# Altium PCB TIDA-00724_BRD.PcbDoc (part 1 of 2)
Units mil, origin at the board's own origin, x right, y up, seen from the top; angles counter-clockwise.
Board outline 4500 x 3350 mil, 4 copper layers (Top Layer, Signal Layer 1, Signal Layer 2, Bottom Layer), stack 61.634 mil thick; 147 components, 76 nets, 383 pads, 213 vias.
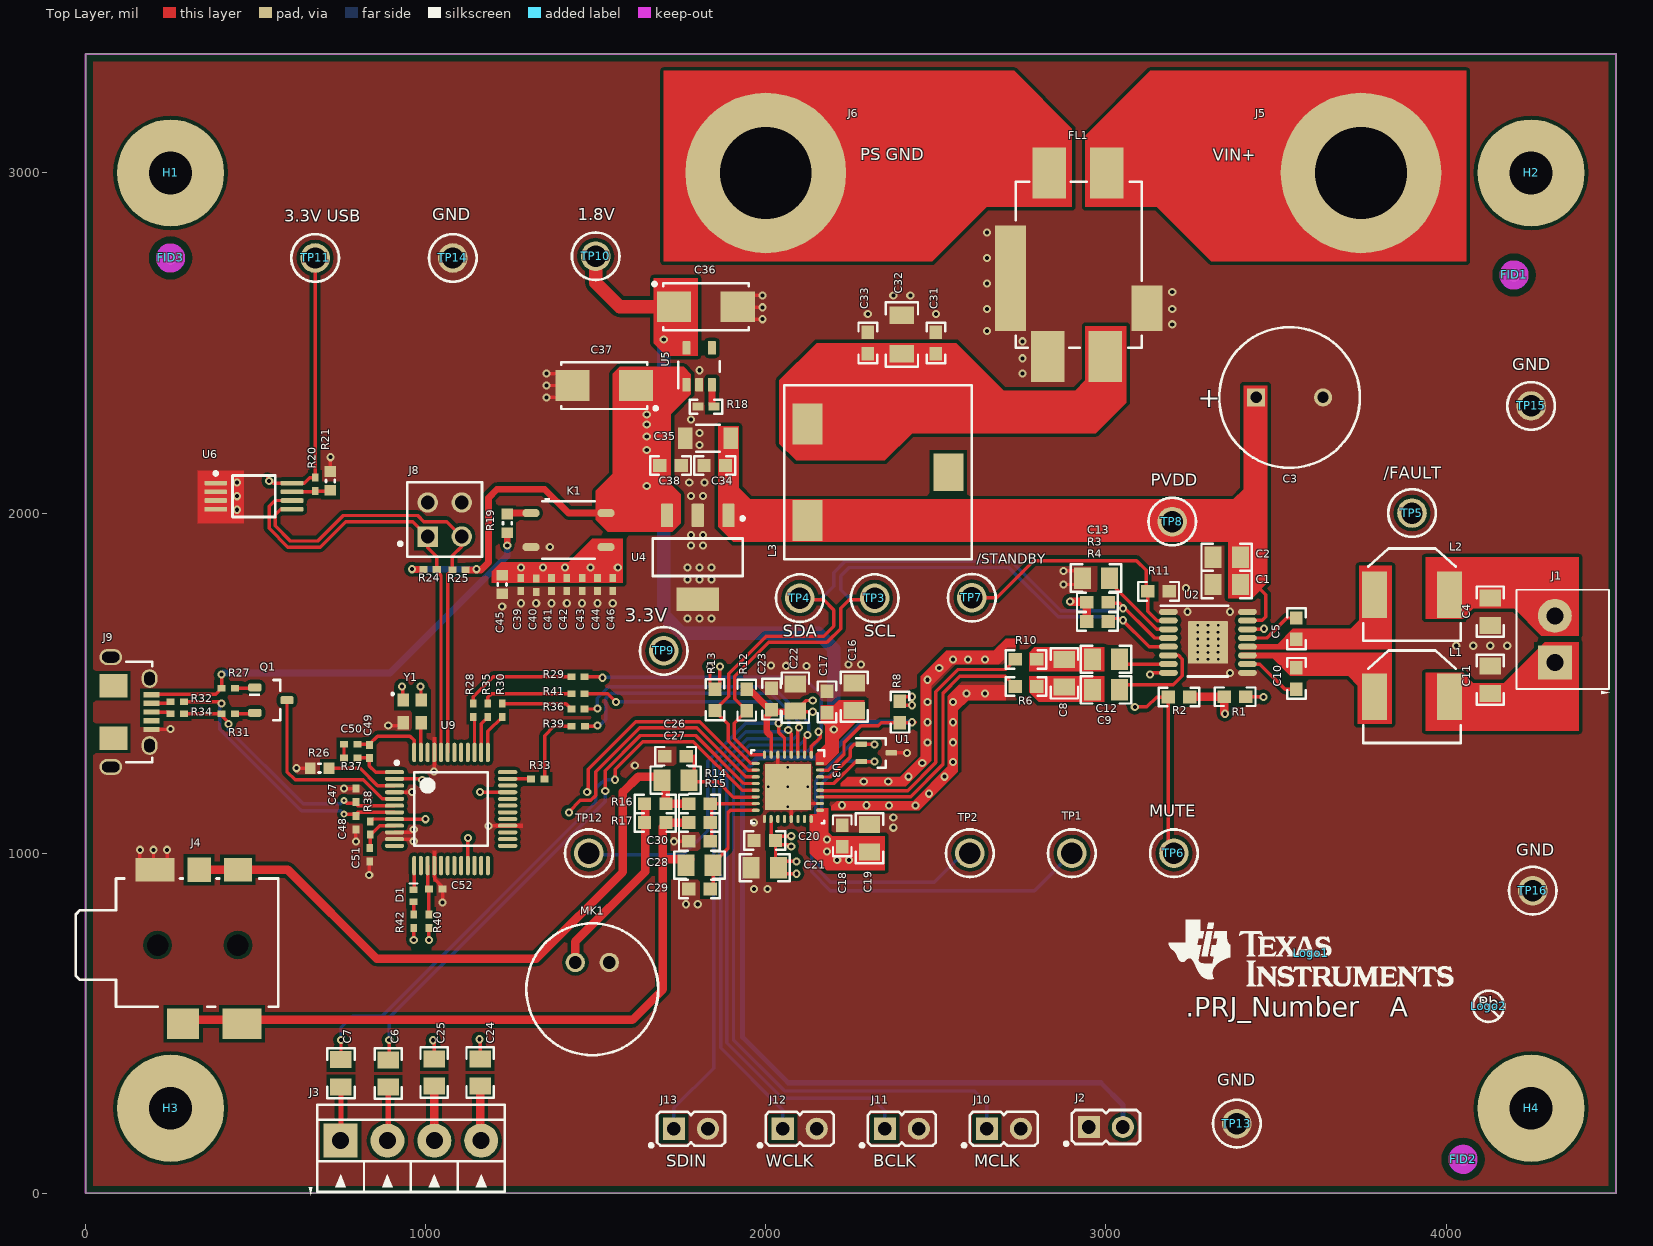
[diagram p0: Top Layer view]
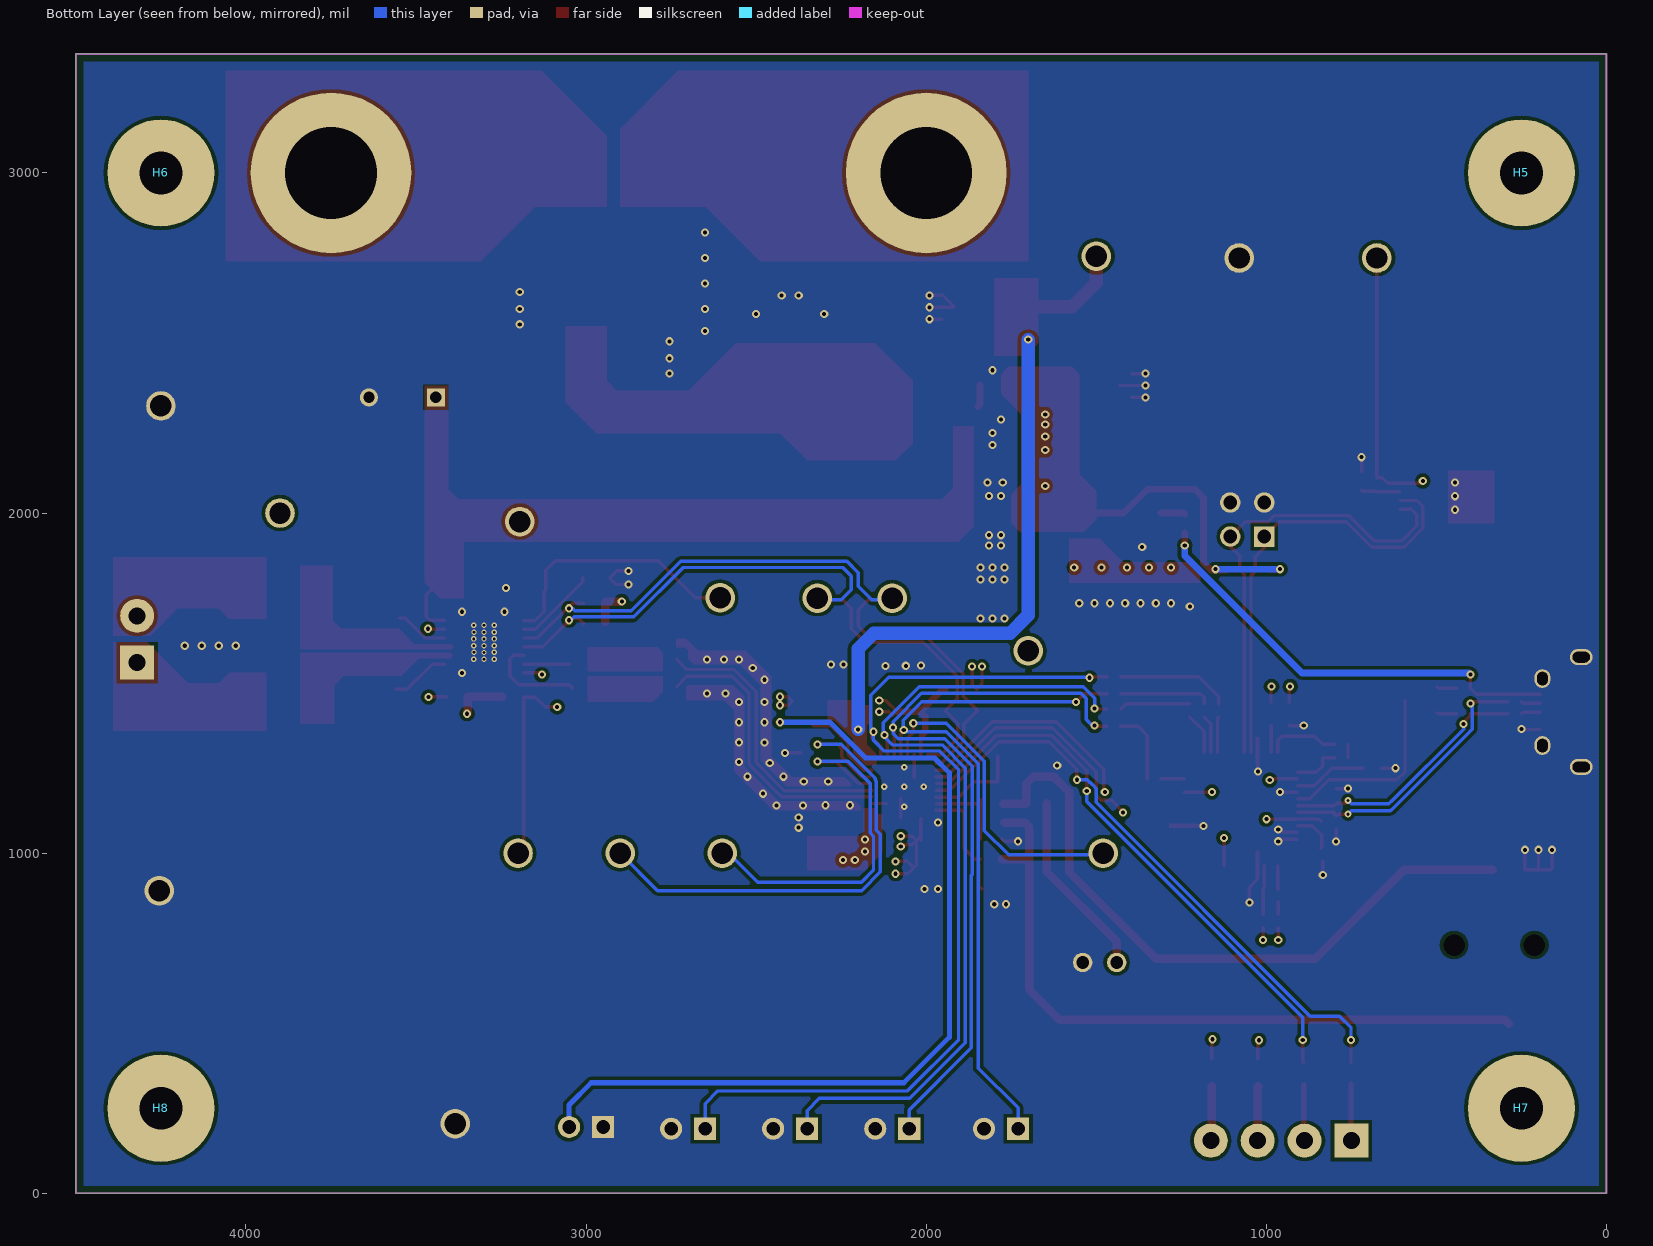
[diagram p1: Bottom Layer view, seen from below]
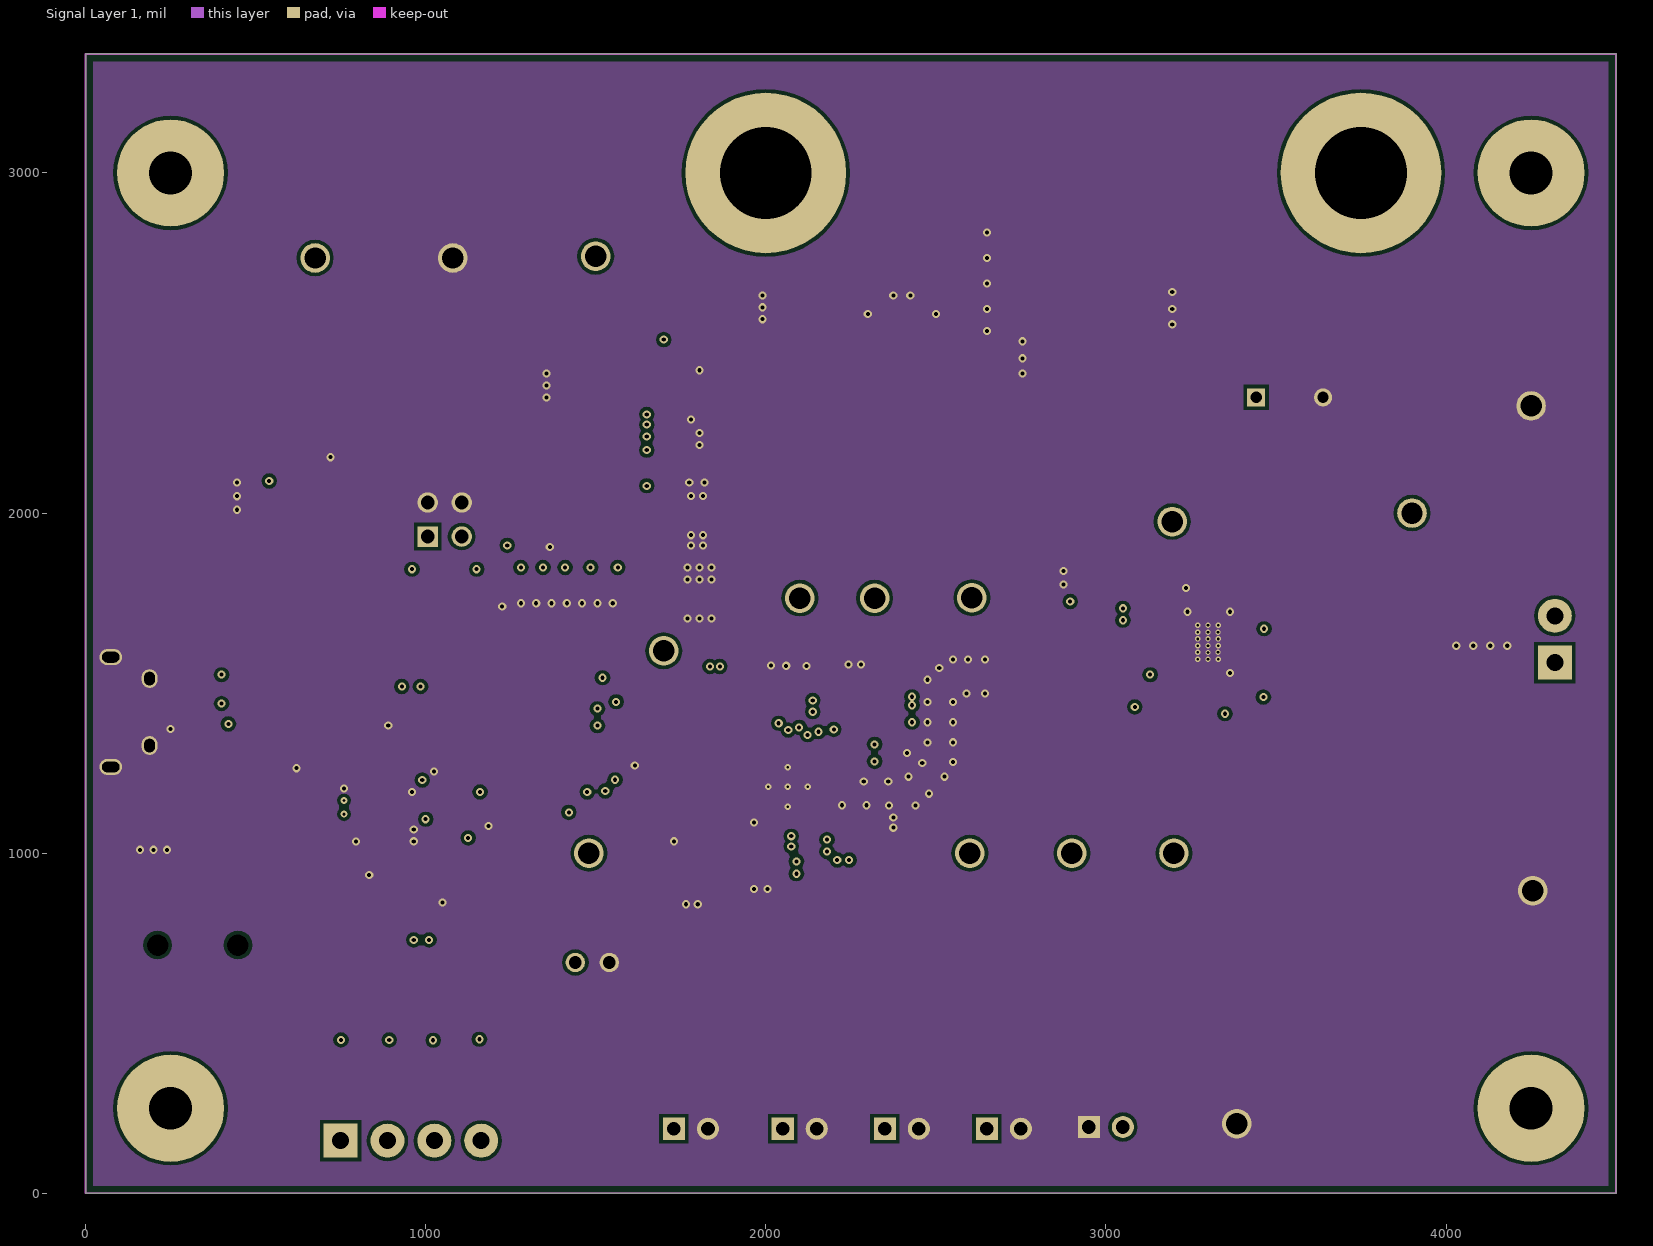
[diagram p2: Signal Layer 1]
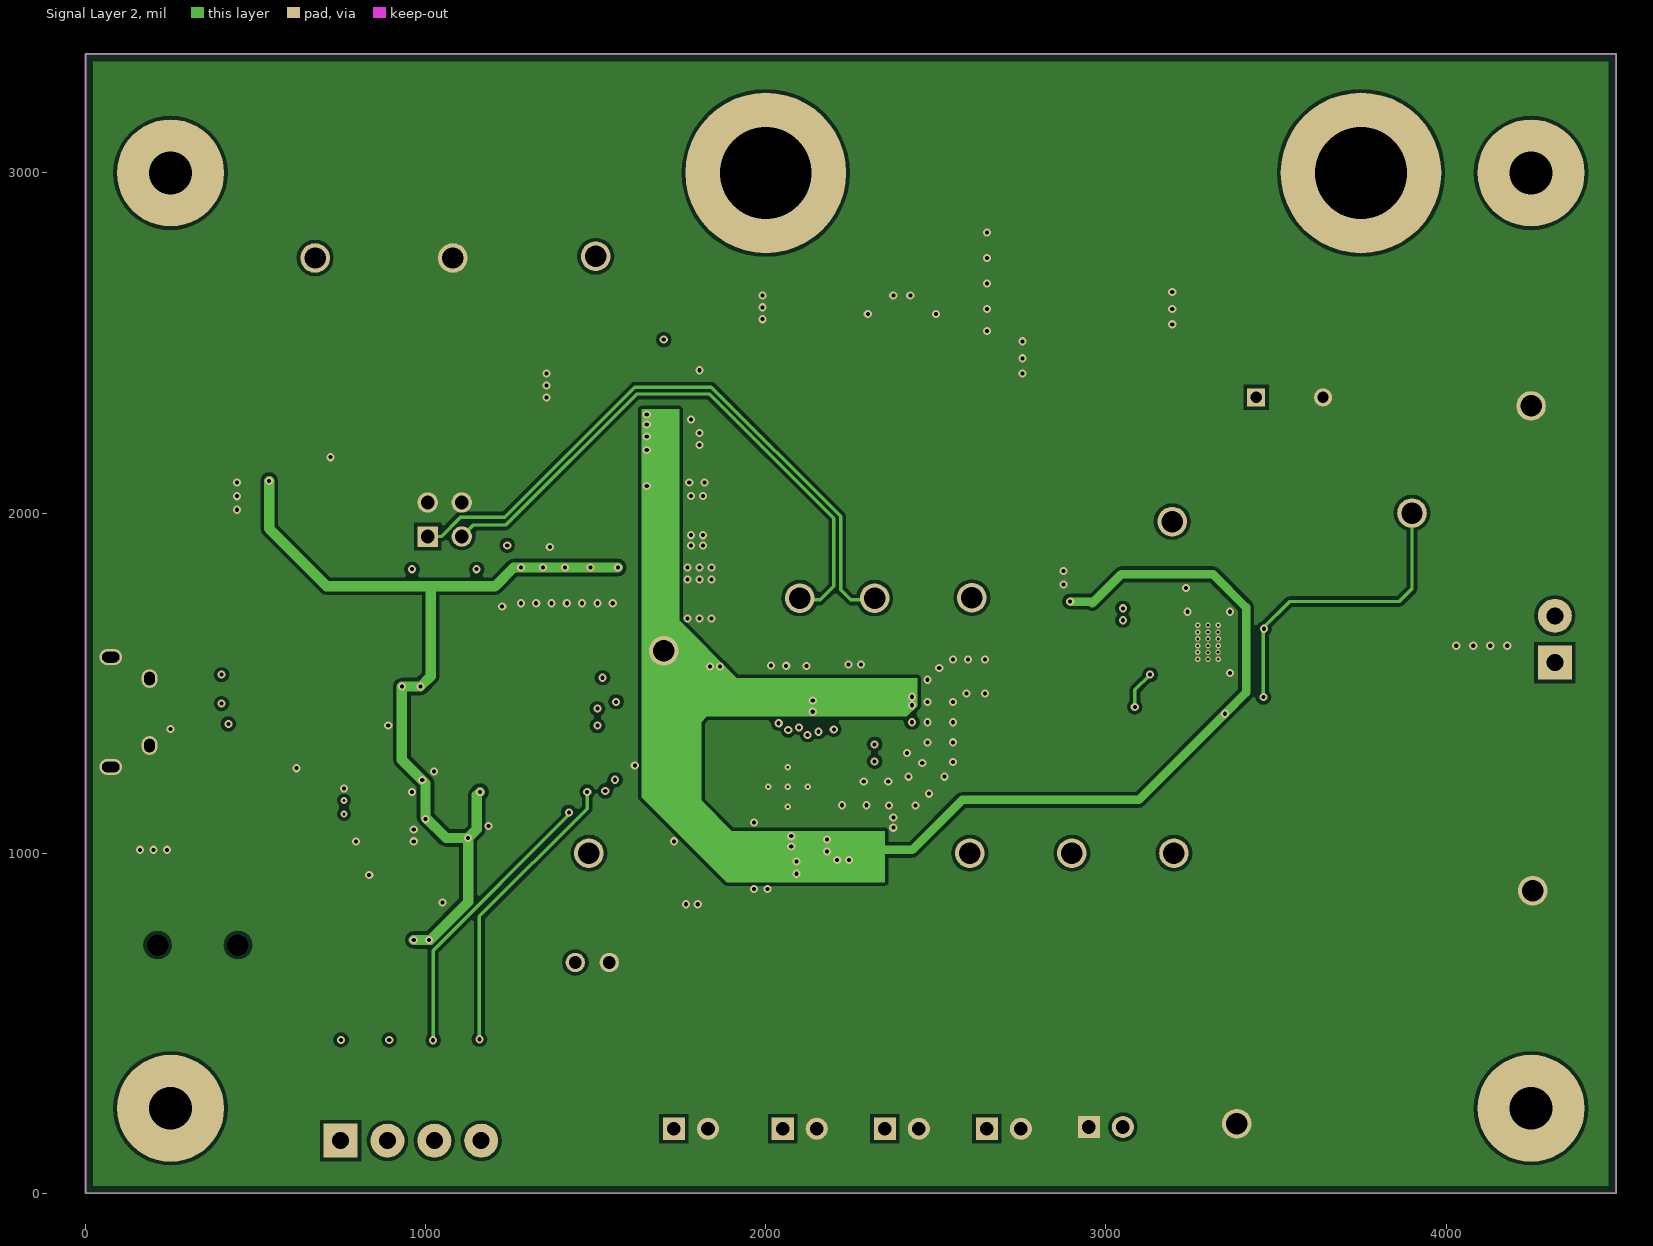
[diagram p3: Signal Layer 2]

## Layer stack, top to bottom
Top Solder: solder mask 0.4, Solder Resist, Dk 3.5
Top Layer: signal copper 1.4
Dielectric1: prepreg 13, FR-4, Dk 4.2
Signal Layer 1: signal copper 1.417
Dielectric 3: core 30, FR-4, Dk 4.2
Signal Layer 2: signal copper 1.417
Dielectric 2: prepreg 13, FR-4, Dk 4.2
Bottom Layer: signal copper 1.4
Bottom Solder: solder mask 0.4, Solder Resist, Dk 3.5

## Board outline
0,0 0,3350 4500,3350 4500,0

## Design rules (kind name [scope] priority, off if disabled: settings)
AcuteAngle [All] p1: minimum=4.50000000000000E+0001 checktracksonly=FALSE
AssemblyTestPointUsage [All] p1: valid=2
Clearance Clearance_Keepouts [((IsTrack Or IsArc) And Not InPoly) And IsFree and IsKeepOut vs ((IsTrack Or IsArc) And Not InPoly) And IsFree and IsKeepOut] p1: gap=0
Clearance Clearance_BoardEdge_MountingHoles [OnCopper and InComponentClass('Mounting Holes') vs IsKeepOut] p2: gap=20
Clearance Clearance_BoardEdge_Poly [OnCopper and InPoly vs IsKeepOut] p3: gap=20
Clearance Clearance_BoardEdge [OnCopper and Not InComponentClass('Logo') and not InComponentClass('FiducialMark') and not InRegion(1000,500,4000,800) and Not IsKeepout vs IsKeepOut] p4: gap=20
Clearance Clearance_Poly [InPolygon] p5: gap=10
Clearance [All] p6: gap=7.87
ComponentClearance ComponentClearance_MountingHoles_FiducialMarks [InComponentClass('Mounting Holes') vs InComponentClass('FiducialMark')] p1: gap=20 collisioncheckmode=3 verticalgap=10 showdistances=FALSE
ComponentClearance ComponentClearance_Shunt [InComponentClass('Header') vs InComponentClass('Shunt')] p2: gap=0 collisioncheckmode=3 verticalgap=0 showdistances=FALSE
ComponentClearance ComponentClearance_Logo [InComponentClass('Logo')] p3: gap=20 collisioncheckmode=3 verticalgap=10 showdistances=FALSE
ComponentClearance ComponentClearance_ScrewToNut [(HasFootprint('NY PMS 440 0025 PH')) vs (HasFootprint('Keystone_1902C'))] p4: gap=5 collisioncheckmode=3 verticalgap=10 showdistances=FALSE
ComponentClearance ComponentClearance_MountingHoles [InComponentClass('Mounting Holes')] p5: gap=20 collisioncheckmode=3 verticalgap=20 showdistances=FALSE
ComponentClearance ComponentClearance_SmallPassives [HasFootprint('0201*') or HasFootprint('0402*') or HasFootprint('0508') or HasFootprint('0603*') or HasFootprint('0612') or HasFootprint('0805*') or HasFootprint('0815*') or HasFootprint('0830*') or HasFootprint('1206*') or HasFootprint('1210*') or HasFootprint('1808*') or HasFootprint('1812*') or HasFootprint('1825*') or HasFootprint('2010*') or HasFootprint('2220*') or HasFootprint('2225*') or HasFootprint('2512*') or HasFootprint('2728*') or HasFootprint('3518*') vs HasFootprint('0201*') or HasFootprint('0402*') or HasFootprint('0508') or HasFootprint('0603*') or HasFootprint('0612') or HasFootprint('0805*') or HasFootprint('0815*') or HasFootprint('0830*') or HasFootprint('1206*') or HasFootprint('1210*') or HasFootprint('1808*') or HasFootprint('1812*') or HasFootprint('1825*') or HasFootprint('2010*') or HasFootprint('2220*') or HasFootprint('2225*') or HasFootprint('2512*') or HasFootprint('2728*') or HasFootprint('3518*')] p6: gap=10 collisioncheckmode=3 verticalgap=10 showdistances=FALSE
ComponentClearance ComponentClearance_THtoSMT [IsThruComponent vs IsSMTComponent] p7: gap=20 collisioncheckmode=3 verticalgap=30 showdistances=FALSE
ComponentClearance ComponentClearance_THtoTH [IsThruComponent vs IsThruComponent] p8: gap=20 collisioncheckmode=3 verticalgap=30 showdistances=FALSE
ComponentClearance [All] p9: gap=20 collisioncheckmode=3 verticalgap=10 showdistances=FALSE
DiffPairsRouting [All] p1: maxlimit=100 minlimit=10 mostfreqgap=10 toplayer_minwidth=15 toplayer_maxwidth=15 toplayer_prefwidth=15 midlayer1_minwidth=15 midlayer1_maxwidth=15 midlayer1_prefwidth=15 midlayer2_minwidth=15 midlayer2_maxwidth=15 midlayer2_prefwidth=15 bottomlayer_minwidth=15 bottomlayer_maxwidth=15 bottomlayer_prefwidth=15 maxuncoupledlength=1000
FabricationTestPointUsage TestPointUsage [All] p1: valid=2 allowmultiple=FALSE
FabricationTestpoint Testpoint [All] p1: side=3 testpointundercomponent=TRUE minsize=40 maxsize=100 preferedsize=60 minholesize=0 maxholesize=40 preferedholesize=32 testpointgrid=1 allowsidetop=TRUE allowsidebottom=TRUE usegrid=TRUE gridtolerance=0.01
FanoutControl Fanout_LCC [IsLCC] p1: bgadir=Out bgaviamode=Centered fanoutstyle=Auto fanoutdirection=Alternating viagrid=1 // Fanout_LCC (Default Rule)
FanoutControl Fanout_BGA [IsBGA] p2: bgadir=Out bgaviamode=Centered fanoutstyle=Auto fanoutdirection=Alternating viagrid=1 // Fanout_BGA (Default Rule)
FanoutControl Fanout_Default [All] p4: bgadir=Out bgaviamode=Centered fanoutstyle=Auto fanoutdirection=Alternating viagrid=1 // Fanout_Default (Default Rule)
FanoutControl Fanout_Small [(CompPinCount < 5)] p5: bgadir=Out bgaviamode=Centered fanoutstyle=Auto fanoutdirection=OutThenIn viagrid=1 // Fanout_Small (Default Rule)
HoleSize [All] p1: absolutevalues=TRUE maxlimit=300 minlimit=5 maxpercent=80.000 minpercent=20.000
MinimumAnnularRing MinimumAnnularRing_ThermalPadVias [IsVia and InAnyComponent] p1: minimumring=3
MinimumAnnularRing [All] p2: minimumring=3
MinimumSolderMaskSliver MinimumSolderMaskSliver_Logo [InComponentClass('Logo') vs InComponentClass('Logo')] p1: minsoldermaskwidth=0.7
MinimumSolderMaskSliver [All] p2: minsoldermaskwidth=3
PlaneClearance [All] p1: clearance=10
PlaneConnect [All] p1: planeconnectstyle=Direct reliefexpansion=10 reliefentries=4 reliefconductorwidth=10 reliefairgap=10
PolygonConnect [All] p1: connectstyle=Direct reliefconductorwidth=10 reliefentries=4 polygonreliefangle="90 Angle" airgapwidth=10
RoutingVias ThermalPadVias [IsVia and InAnyComponent] p1: holewidth=7.87 width=19.68 viastyle="Through Hole" minholewidth=5 minwidth=15 maxholewidth=12.99 maxwidth=23.62
RoutingVias [All] p2: holewidth=16 width=34 viastyle="Through Hole" minholewidth=5 minwidth=15 maxholewidth=40 maxwidth=65
SilkToBoardRegionClearance [Not ((IsComment or IsDesignator) And (Hide <> 'False')) and not InRegion(1000,500,4000,800)] p1:
SilkToSilkClearance SilkToSilkClearance_Pb-FreeLogo [(HasFootprint('Pb-Free_Overlay_Medium') OR HasFootprint('Pb-Free_Overlay_Small')) vs (HasFootprint('Pb-Free_Overlay_Medium') OR HasFootprint('Pb-Free_Overlay_Small'))] p1: silktosilkclearance=0
SilkToSilkClearance [All] p2: silktosilkclearance=4
SilkToSolderMaskClearance "Silk to Solder Mask Opening" [All] p1: minsilkscreentomaskgap=2.5 clearancetoexposedcopper=FALSE
SolderMaskExpansion [All] p1: expansion=1.97
UnpouredPolygon [All] p1: allowunpoured=FALSE
Width [All] p1: maxlimit=100 minlimit=6 preferedwidth=10 checkconnectedcopper=TRUE
13 further rules are at their usual default settings.

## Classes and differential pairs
component class AssemblyNote: ZZ1 ZZ2 ZZ3
component class FiducialMark: FID1 FID2 FID3
component class eCall_Audio_Hardware: FID1 FID2 FID3 H1 H2 H3 H4 H5 H6 H7 H8 Logo1 Logo2 ZZ1 ZZ2 ZZ3
component class Logo: Logo1
component class "Mounting Holes": H1 H2 H3 H4
component class eCall_Audio: C1 C2 C3 C4 C5 C6 C7 C8 C9 C10 C11 C12 C13 C16 C17 C18 C19 C20 C21 C22 C23 C24 C25 C26 C27 C28 C29 C30 J1 J2 J3 J4 L1 L2 MK1 R1 R2 R3 R4 R6 R8 R10 R11 R12 R13 R14 R15 R16 R17 TP1 TP2 TP3 TP4 TP5 TP6 TP7 TP12 U1 U2 U3
component class Header: J2 J8 J10 J11 J12 J13
component class eCall_Audio_Power: C31 C32 C33 C34 C35 C36 C37 C38 FL1 J5 J6 L3 R18 TP8 TP9 TP10 U4 U5
component class eCall_Audio_TAS1020: C39 C40 C41 C42 C43 C44 C45 C46 C47 C48 C49 C50 C51 C52 D1 J8 J9 J10 J11 J12 J13 K1 Q1 R19 R20 R21 R24 R25 R26 R27 R28 R29 R30 R31 R32 R33 R34 R35 R36 R37 R38 R39 R40 R41 R42 TP11 TP13 TP14 TP15 TP16 U6 U9 Y1

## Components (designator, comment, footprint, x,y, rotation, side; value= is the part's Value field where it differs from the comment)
C1 "C0805C106K9PAC" 0805_HV 3355,1790 r180 top
C2 "GRM21BR71H105KA12L" 0805_HV 3355,1870 r180 top
C3 "EKZE500ELL331MJ25S" KZE_1000x2500 3540,2340 r0 top
C4 "EMK212B7225KG-T" 0805_HV 4130,1710 r90 top
C5 "C1608X7R1H224K080AB" 0603 3560,1660 r90 top
C6 "C2012X7R2A104K" 0805_HV 890,352 r90 top
C7 "C2012X7R2A104K" 0805_HV 751,353 r90 top
C8 "EMK212B7225KG-T" 0805_HV 2878,1529 r90 top
C9 "EMK212B7225KG-T" 0805_HV 3000,1480 r180 top
C10 "C1608X7R1H224K080AB" 0603 3560,1514 r270 top
C11 "EMK212B7225KG-T" 0805_HV 4130,1510 r90 top
C12 "EMK212B7225KG-T" 0805_HV 3000,1570 r180 top
C13 "GRM21BR71H105KA12L" 0805_HV 2971,1809 r180 top
C16 "C0805C106K9PAC" 0805_HV 2260,1460 r90 top
C17 "C1608X7R1C104K" 0603 2180,1445 r90 top
C18 "C1608X7R1C104K" 0603 2225,1051 r90 top
C19 "C0805C106K9PAC" 0805_HV 2305,1044 r90 top
C20 "C1608X7R1C104K" 0603 1997.01,1037.46 r180 top
C21 "C0805C106K9PAC" 0805_HV 1997.01,957.46 r180 top
C22 "C0805C106K9PAC" 0805_HV 2087.01,1457.46 r90 top
C23 "C1608X7R1C104K" 0603 2017,1453 r90 top
C24 "C2012X7R2A104K" 0805_HV 1160,355 r90 top
C25 "C2012X7R2A104K" 0805_HV 1025,355 r90 top
C26 "DNP" 0603 1735,1285 r180 top
C27 "C2012X7R2A104K" 0805_HV 1735,1215 r0 top
C28 "C2012X7R2A104K" 0805_HV 1805,965 r0 top
C29 "DNP" 0603 1805,895 r180 top
C30 "DNP" 0603 1805,1035 r180 top
C31 "GRM188R71H222KA01D" 0603 2500,2500 r90 top
C32 "GRM31CR71E475KA88L" 1206 2400,2525 r90 top
C33 "GRM188R71E823KA01D" 0603 2300,2500 r90 top
C34 "GRM188R71E104KA01D" 0603 1850,2140 r180 top
C35 "GRM31CR61H106KA12L" 1206_190 1830,2220 r180 top
C36 "TPSC475K035R0600" 6032-28 1824.05,2606.56 r0 top
C37 "TPSC475K035R0600" 6032-28 1525,2375 r180 top
C38 "GRM188R71E104KA01D" 0603 1720,2140 r0 top
C39 "GRM155R71C104KA88D" 0402L 1280,1790 r270 top
C40 "GRM155R71C104KA88D" 0402L 1325,1788.19 r270 top
C41 "GRM155R71C104KA88D" 0402L 1370,1790 r270 top
C42 "GRM155R71C104KA88D" 0402L 1415,1790 r270 top
C43 "GRM155R71C104KA88D" 0402L 1460,1790 r270 top
C44 "GRM155R71C104KA88D" 0402L 1505,1790 r270 top
C45 "C1608X5R1A106M" 0603L 1225,1790 r270 top
C46 "C1005X5R0J105M" 0402L 1550,1790 r90 top
C47 "GRM1555C1E470JA01D" 0402L 795,1170 r270 top
C48 "GRM1555C1E470JA01D" 0402L 795,1090 r90 top
C49 "GRM1555C1H101JA01D" 0402L 835,1299 r90 top
C50 "GRM1555C1H102JA01D" 0402L 779.69,1320 r180 top
C51 "C1005X5R0J105M" 0402L 836,995 r90 top
C52 "GRM155R71C104KA88D" 0402L 1029.69,895 r0 top
D1 "USB-LOCK" LED_SMLP12_BLUE 964.69,875 r90 top
FID1 "Fiducial" Fiducial10-20 4200,2700 r0 top
FID2 "Fiducial" Fiducial10-20 4050,100 r0 top
FID3 "Fiducial" Fiducial10-20 250,2750 r0 top
FL1 "BNX022-01L" FIL_BNX02X 2920,2730 r270 top
H1 "NY PMS 440 0025 PH" "NY PMS 440 0025 PH" 250,3000 r0 top locked
H2 "NY PMS 440 0025 PH" "NY PMS 440 0025 PH" 4250,3000 r0 top locked
H3 "NY PMS 440 0025 PH" "NY PMS 440 0025 PH" 250,250 r0 top locked
H4 "NY PMS 440 0025 PH" "NY PMS 440 0025 PH" 4250,250 r0 top locked
H5 "1902C" Keystone_1902C 250,3000 r180 bottom locked
H6 "1902C" Keystone_1902C 4250,3000 r180 bottom locked
H7 "1902C" Keystone_1902C 250,250 r180 bottom locked
H8 "1902C" Keystone_1902C 4250,250 r180 bottom locked
J1 "ED555/2DS" TERM_BLK_ED555-2DS 4320,1560 r90 top
J2 "PBC02SAAN" Sullins_PBC02SAAN 3000,195 r90 top
J3 "ED555/4DS" TERM_BLK_ED555-4DS 750,155 r0 top
J4 "SJ1-3515-SMT-TR-PI" CUI_SJ1-351x-SMT-PI 330,730 r0 top
J5 "VIN+" Tenma_SPC15363 3750,3000 r0 top
J6 "PS GND" Tenma_SPC15354 2000,3000 r0 top
J8 "I2C" Sullins_PEC02DAAN 1056,1981 r90 top
J9 "USB-IN" CONN_USB_DX4R205JJA 25,1415 r270 top
J10 "MCLK" Sullins_PBC02SAAN 2700,190 r90 top
J11 "BCLK" Sullins_PBC02SAAN 2400,190 r90 top
J12 "WCLK" Sullins_PBC02SAAN 2100,190 r90 top
J13 "SDIN" Sullins_PBC02SAAN 1780,190 r90 top
K1 "CPC1002NTR" RELAY_CPC1002N 1420,1950 r0 top
L1 "DFEG7030D-150M" DFEG7030D 3900,1760 r0 top
L2 "DFEG7030D-150M" DFEG7030D 3900,1460 r0 top
L3 "SER1360-103KLB" SER1360 2330,2120 r0 top
Logo1 "Texas Instruments" TI_Stacked_Overlay_Small 3603.08,706.53 r0 top
Logo2 "Pb-Free Symbol" Pb-Free_Overlay_Small 4125,550 r0 top
MK1 "CMA-4544PF-W" CUI_CMA-4544PF-W 1490,600 r270 top
Q1 "MMBT2222A" SOT-23 545,1450 r0 top
R1 "CRCW0603100KJNEA" 0603 3380,1460 r0 top
R2 "CRCW0603100KJNEA" 0603 3215,1459 r180 top
R3 "CRCW060310K0JNEA" 0603 2975,1738 r0 top
R4 "CRCW060310K0JNEA" 0603 2975,1681 r0 top
R6 "MCR03EZPJ000" 0603 2765,1490 r180 top
R8 "CRCW0603100KJNEA" 0603 2394.2,1414.98 r90 top
R10 "MCR03EZPJ000" 0603 2765,1570 r180 top
R11 "CRCW0603100KJNEA" 0603 3155,1770 r180 top
R12 "RC0603JR-072K7L" 0603 1944,1450 r270 top
R13 "RC0603JR-072K7L" 0603 1851,1451 r270 top
R14 "RC0603JR-072K2L" 0603 1805,1145 r0 top
R15 "RC0603JR-072K2L" 0603 1805,1090 r180 top
R16 "MCR03EZPJ000" 0603 1675,1145 r0 top
R17 "MCR03EZPJ000" 0603 1675,1090 r0 top
R18 "ERJ-2GE0R00X" 0402 1824.05,2313.03 r0 top
R19 "CRCW06034K99FKEA" 0603L 1240,1970 r270 top
R20 "CRCW0402100KFKED" 0402L 675,2084.37 r90 top
R21 "CRCW06030000Z0EA" 0603L 720,2094.37 r90 top
R24 "CRCW04024K99FKED" 0402L 1013,1834 r180 top
R25 "CRCW04024K99FKED" 0402L 1098,1833 r0 top
R26 "CRCW06030000Z0EA" 0603L 688,1250 r180 top
R27 "CRCW040215K0FKED" 0402L 420,1485 r0 top
R28 "CRCW040249R9FKED" 0402L 1140,1420 r90 top
R29 "CRCW04020000Z0ED" 0402L 1448,1519 r180 top
R30 "CRCW040249R9FKED" 0402L 1225,1420 r90 top
R31 "CRCW04021K50FKED" 0402L 420,1410 r180 top
R32 "CRCW040227R4FKED" 0402L 270,1445 r0 top
R33 "CRCW040249R9FKED" 0402L 1330,1218 r0 top
R34 "CRCW040227R4FKED" 0402L 270,1410 r0 top
R35 "CRCW040249R9FKED" 0402L 1183,1420 r90 top
R36 "CRCW04020000Z0ED" 0402L 1448,1424 r180 top
R37 "CRCW04023K09FKED" 0402L 779.69,1280 r0 top
R38 "CRCW0402100KFKED" 0402L 837,1074 r90 top
R39 "CRCW04020000Z0ED" 0402L 1449,1373 r180 top
R40 "CRCW040210K0FKED" 0402L 1009.69,800 r270 top
R41 "CRCW04020000Z0ED" 0402L 1448,1469 r180 top
R42 "CRCW0402360RJNED" 0402L 964.69,800 r90 top
TP1 "5009" Keystone5009 2900,1000 r0 top
TP2 "5009" Keystone5009 2600,1000 r0 top
TP3 "SCL" Keystone5009 2320,1750 r0 top
TP4 "SDA" Keystone5009 2100,1750 r0 top
TP5 "/FAULT" Keystone5009 3900,2000 r0 top
TP6 "MUTE" Keystone5009 3200,1000 r0 top
TP7 "/STANDBY" Keystone5009 2606,1751 r0 top
TP8 "PVDD" Keystone5009 3195,1975 r0 top
TP9 "3.3V" Keystone5009 1700,1595 r0 top
TP10 "1.8V" Keystone5009 1500,2755 r0 top
TP11 "3.3V USB" Keystone5009 675,2750 r0 top
TP12 "DOUT" Keystone5009 1480,1000 r0 top
TP13 "GND" Keystone5006 3385,205 r0 top
TP14 "GND" Keystone5006 1080,2750 r0 top
TP15 "GND" Keystone5006 4250,2315 r0 top
TP16 "GND" Keystone5006 4255,890 r0 top
U1 "TPD2E007DCKR" DCK0003A_N 2325,1295 r0 top
U2 "TAS5411QPWPRQ1" PWP0016B_N 3300,1620 r0 top
U3 "6PAIC3104IRHBRQ1" RHB0032E 2065,1195 r270 top
U4 "TPS7B6933QDCYRQ1" DCY0004A_N 1800,1870 r270 top
U5 "TPS76918QDBVRQ1" DBV0005A_N 1804.05,2431.56 r90 top
U6 "24LC512-I/ST" TSSOP-8 495,2049.69 r0 top
U9 "TAS1020BPFB" PFB0048A_N 1074.69,1130 r0 top
Y1 "625L3I006M00000" OSC_CTS_625 961,1417 r0 top
ZZ1 "These assemblies are ESD sensitive, ESD precautions shall be observed." AssemblyNote 185,3829.11 r0 top
ZZ2 "These assemblies must be clean and free from flux and all contaminants. Use of no clean flux is not acceptable." AssemblyNote 185,3740.56 r0 top
ZZ3 "These assemblies must comply with workmanship standards IPC-A-610 Class 2, unless otherwise specified." AssemblyNote 185,3652 r0 top

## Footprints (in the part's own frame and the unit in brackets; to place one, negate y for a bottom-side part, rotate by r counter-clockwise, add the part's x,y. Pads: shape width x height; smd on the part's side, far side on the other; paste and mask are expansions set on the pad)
0402 [mm] "0402 from SM-752 data"
  rect 0.8x0.6 smd: 1(-0.6,0) 2(0.6,0)
  silkscreen extent -1.22,-0.52 1.22,0.52, body extent -0.55,-0.3 0.55,0.3, height 0.6
0402L [mm] "0402 from SM-752 data"
  rect 0.6x0.5 smd: 1(-0.5,0) 2(0.5,0)
  body extent -0.55,-0.3 0.55,0.3, height 0.6
0603 [mm] "0603 from SM-752 data"
  rect 1x0.95 smd: 1(-0.8,0) 2(0.8,0)
  silkscreen extent -1.52,-0.69 1.52,0.69, body extent -0.87,-0.47 0.87,0.47, height 1
0603L [mm] "0603 from SM-752 data"
  rect 0.8x0.85 smd: 1(-0.7,0) 2(0.7,0)
  silkscreen extent -0.07,-0.33 0.07,0.33, body extent -0.87,-0.47 0.87,0.47, height 1
0805_HV [mil] "0805 with 30mil clearance between pads"
  rect 50x63 smd: 1(-40,0) 2(40,0)
  silkscreen extent -74,-40 74,40, body extent -43,-29 43,29, height 57
1206 [mm] "1206 from SM-752 data"
  rect 1.3x1.85 smd: 1(-1.45,0) 2(1.45,0)
  silkscreen extent -2.4,-1.21 2.4,1.21, body extent -1.7,-0.9 1.7,0.9, height 1.35
1206_190 [mm] "1206_190"
  rect 1.1x1.6 smd: 1(-1.7,0) 2(1.7,0)
  silkscreen extent -0.9,-1 0.9,1, body extent -1.75,-0.95 1.75,0.95, height 1.9
6032-28 [mm] "Medium Density IPC based on Vishay Sprague 293D datasheet."
  rect 2.55x2.3 smd: 1(-2.375,0) 2(2.375,0)
  silkscreen extent -3.96,-1.75 3.2,1.82, body extent -3.15,-1.75 3.15,1.75, height 2.8
AssemblyNote [mil] "Assembly Note"
CONN_USB_DX4R205JJA [mm] "Connecctor, USB-AB, 5 Pos"
  rect 0.4x1.2 smd mask+0.064: 1(-1.3,4.3) 2(-0.65,4.3) 3(0,4.3) 4(0.65,4.3) 5(1.3,4.3)
  oval 1.4x1.2 hole 0.8 slot 1 at 0 deg: 6(-2.5,4.15) 7(2.5,4.15)
  oval 1.2x1.7 hole 0.8 slot 1.3 at 90 deg: 8(-4.1,1.25) 9(4.1,1.25)
  rect 1.73x2.1 smd: M1(-1.96,1.45) M2(1.96,1.45)
  silkscreen extent -3.76,2.4 3.76,4.35, body extent -4.3,-0.65 4.3,4.45, height 2.69
CUI_CMA-4544PF-W [mm] "THD, 2-Leads, Dia 9.85mm, Pin Spacing 2.54mm"
  round 1.45 hole 0.95: 1(-2,1.27) 2(-2,-1.27)
  silkscreen extent -4.92,-4.92 4.92,4.92, body extent -4.85,-4.85 4.85,4.85, height 4.7
CUI_SJ1-351x-SMT-PI [mm] "CUI, Stereo Audio Jack, pink"
  rect 2.9x1.75 smd: 1(-3.2,5.625)
  rect 2.9x2.25 smd: 2(3.3,-5.875)
  rect 2.1x1.75 smd: 3(3,5.625)
  rect 2.4x2.25 smd: 4(-1.1,-5.875)
  rect 1.75x1.8 smd: 5(0.1,5.625)
  round 1 hole 1.6 unplated: MH1(-3,0) MH2(3,0)
  silkscreen extent -9.1,-4.6 6,4.97, body extent -9,-6 6,6, height 5.1
DBV0005A_N [mm] "SOT23, 5-Leads, Body 2.9x1.6mm, Pitch 0.95mm, Lead Span 2.8mm, IPC Medium Density"
  rrect17% 1x0.6 smd: 1(-1.375,0.95) 2(-1.375,0) 3(-1.375,-0.95) 4(1.375,-0.95) 5(1.375,0.95)
  silkscreen extent -1.63,-1.55 0.38,1.55, body extent -1.42,-1.46 1.42,1.46, height 1.09
DCK0003A_N [mm] "SOT23, 3-Leads, Body 2.0x1.25mm, Pitch 0.65mm, Lead Span 2.1mm, IPC Medium Density"
  rrect25% 0.85x0.4 smd: 1(-1.125,0.65) 2(-1.125,-0.65) 3(1.125,0)
  silkscreen extent -1.48,-1.1 0.7,1.1, body extent -1.06,-1 1.06,1, height 1.1
DCY0004A_N [mm] "SOT223/SC73, 4-Leads, Body 6.5x3.5mm, Pitch 2.3mm, Lead Span 7mm, IPC Medium Density"
  rrect11% 1.75x0.9 smd: 1(-3.125,2.3) 2(-3.125,0) 3(-3.125,-2.3)
  rrect6% 1.75x3.2 smd: 4(3.125,0)
  silkscreen extent -3.02,-3.35 1.4,3.48, body extent -3.48,-3.25 3.48,3.25, height 1.68
DFEG7030D [mm] "SMD, 2-Leads, Body 7x6.6mm"
  rect 1.9x3.5 smd: 1(-2.8,0) 2(2.8,0)
  silkscreen extent -3.65,-3.45 3.65,3.45, body extent -3.65,-3.45 3.65,3.45, height 3
Fiducial10-20 [mm]
  round 1 smd mask+0.5: 1(0,0)
  Top Layer keep-out circle w1.178: c0,0 r0.5
FIL_BNX02X [mm] "MuRata filter"
  rect 3.8x2.5 smd: 1(-6.85,2.1) 2(6.85,2) 3(-6.85,-2.2) 4(6.85,-2.3)
  rect 3.4x2.3 smd: 5(3.25,5.1)
  rect 7.9x2.3 smd: 6(1,-5.1)
  silkscreen extent -6.2,-4.7 6.2,4.7, body extent -6.05,-4.55 6.05,4.55, height 3.1
Keystone5006 [mil] "Keystone Compact loops"
  round 87 hole 63: 1(0,0)
  silkscreen extent -70,-70 70,70, body extent -63,-63 62,63, height 225
Keystone5009 [mil] "Keystone Compact loops"
  round 87 hole 63: 1(0,0)
  silkscreen extent -70,-70 70,70, body extent -63,-63 62,63, height 225
Keystone_1902C [mil] "Hex Standoff, 4-40 threaded, nylon"
  body extent -145,-126 146,126, height 501
KZE_1000x2500 [mm] "TH, 2-Leads, Dia 10mm, Lead Spacing 5mm"
  rect 1.35x1.35 hole 0.85: 1(-2.5,0)
  round 1.35 hole 0.85: 2(2.5,0)
  silkscreen extent -5.25,-5.25 5.25,5.25, body extent -5.21,-5.24 5.24,5.24, height 26.51
LED_SMLP12_BLUE [mm] "Rohm Semiconductor"
  rect 0.5x0.6 smd mask+0.08: 1(-0.45,0) 2(0.45,0)
  silkscreen extent 0.92,-0.3 0.92,0.3, body extent -0.55,-0.35 0.55,0.35, height 0.25
"NY PMS 440 0025 PH" [mm] "4-40 nylon screw and mounting hole"
  round 8 hole 3.2: 1(0,0)
  body extent -3.3,-3.3 3.3,3.3, height 2.69
OSC_CTS_625 [mm] "CTS"
  rect 0.85x1 smd: 1(-0.675,0.85) 2(-0.675,-0.85) 3(0.675,-0.85) 4(0.675,0.85)
  silkscreen extent -1.52,1.25 -1.43,1.35, body extent -1.1,-1.35 1.1,1.35, height 1.02
Pb-Free_Overlay_Small [mil]
  silkscreen extent -46,-46 46,46
PFB0048A_N [mm] "Thin QFP, 48-Leads, Body 7x7mm, Pitch 0.5mm, IPC Medium Density"
  oval 1.45x0.3 smd: 1(-4.225,2.75) 2(-4.225,2.25) 3(-4.225,1.75) 4(-4.225,1.25) 5(-4.225,0.75) 6(-4.225,0.25) 7(-4.225,-0.25) 8(-4.225,-0.75) 9(-4.225,-1.25) 10(-4.225,-1.75) 11(-4.225,-2.25) 12(-4.225,-2.75) 25(4.225,-2.75) 26(4.225,-2.25) 27(4.225,-1.75) 28(4.225,-1.25) 29(4.225,-0.75) 30(4.225,-0.25) 31(4.225,0.25) 32(4.225,0.75) 33(4.225,1.25) 34(4.225,1.75) 35(4.225,2.25) 36(4.225,2.75)
  oval 0.3x1.45 smd: 13(-2.75,-4.225) 14(-2.25,-4.225) 15(-1.75,-4.225) 16(-1.25,-4.225) 17(-0.75,-4.225) 18(-0.25,-4.225) 19(0.25,-4.225) 20(0.75,-4.225) 21(1.25,-4.225) 22(1.75,-4.225) 23(2.25,-4.225) 24(2.75,-4.225) 37(2.75,4.225) 38(2.25,4.225) 39(1.75,4.225) 40(1.25,4.225) 41(0.75,4.225) 42(0.25,4.225) 43(-0.25,4.225) 44(-0.75,4.225) 45(-1.25,4.225) 46(-1.75,4.225) 47(-2.25,4.225) 48(-2.75,4.225)
  silkscreen extent -4.17,-2.75 2.75,3.57, body extent -4.5,-4.5 4.5,4.5, height 1.07
PWP0016B_N [mm] "TSOP, 16-Leads, Body 5x4.4mm, Pitch 0.65mm, Thermal Pad 3x3 mm, IPC Medium Density"
  rrect100% 1.4x0.45 smd: 1(-2.95,2.275) 2(-2.95,1.625) 3(-2.95,0.975) 4(-2.95,0.325) 5(-2.95,-0.325) 6(-2.95,-0.975) 7(-2.95,-1.625) 8(-2.95,-2.275) 9(2.95,-2.275) 10(2.95,-1.625) 11(2.95,-0.975) 12(2.95,-0.325) 13(2.95,0.325) 14(2.95,0.975) 15(2.95,1.625) 16(2.95,2.275)
  rrect3% 3x3.15 smd: 17(0,0)
  silkscreen extent -3.52,-2.55 1.5,2.73, body extent -3.21,-2.5 3.21,2.5, height 1
RELAY_CPC1002N [mm] "SOP, 4-Lead, Body 4.089x3.81mm, Pitch 2.54mm"
  oval 1.3x0.6 smd: 1(-2.8,1.27) 2(-2.8,-1.27) 3(2.8,-1.27) 4(2.8,1.27)
  silkscreen extent -1.94,-2.15 1.94,2.4, body extent -1.94,-2.15 1.94,2.15, height 2.18
RHB0032E [mm] "QFN, 32-Leads, Body 5x5mm, Pitch 0.5mm, Thermal Pad 3.45x3.45mm, TI Recommended"
  oval 0.6x0.24 smd: 1(-2.4,1.75) 2(-2.4,1.25) 3(-2.4,0.75) 4(-2.4,0.25) 5(-2.4,-0.25) 6(-2.4,-0.75) 7(-2.4,-1.25) 8(-2.4,-1.75) 17(2.4,-1.75) 18(2.4,-1.25) 19(2.4,-0.75) 20(2.4,-0.25) 21(2.4,0.25) 22(2.4,0.75) 23(2.4,1.25) 24(2.4,1.75)
  oval 0.24x0.6 smd: 9(-1.75,-2.4) 10(-1.25,-2.4) 11(-0.75,-2.4) 12(-0.25,-2.4) 13(0.25,-2.4) 14(0.75,-2.4) 15(1.25,-2.4) 16(1.75,-2.4) 25(1.75,2.4) 26(1.25,2.4) 27(0.75,2.4) 28(0.25,2.4) 29(-0.25,2.4) 30(-0.75,2.4) 31(-1.25,2.4) 32(-1.75,2.4)
  rect 3.45x3.45 smd paste-1.725: 33(0,0)
  silkscreen extent -2.72,-2.73 2.72,2.73, body extent -2.57,-2.57 2.58,2.58, height 1.01
SER1360 [mm] "SER1360"
  rect 2.26x3.07 smd: 1(-5.26,3.605) 2(-5.26,-3.605)
  rect 2.26x2.77 smd: 3(5.26,0)
  silkscreen extent -7,-6.5 7,6.5, body extent -6.5,-6.45 6.5,6.45, height 5.8
SOT-23 [mm] "SOT23, 3-Leads, Body 2.9x1.3mm, Pitch 0.95mm, Lead Span 2.5mm, IPC Medium Density"
  rrect50% 1x0.6 smd: 1(-1.2,0.95) 2(-1.2,-0.95) 3(1.2,0)
  silkscreen extent -1.63,-1.5 0.7,1.5, body extent -1.16,-1.45 1.21,1.45, height 1
Sullins_PBC02SAAN [mm] "Sullins 100mil, 1x2, 230 mil above insulator"
  rect 1.65x1.65 hole 1.016: 1(0,1.27)
  round 1.65 hole 1.016: 2(0,-1.27)
  silkscreen extent -1.37,-2.54 1.27,3.1, body extent -1.27,-2.54 1.27,2.54, height 8.38
Sullins_PEC02DAAN [mil] "Sullins Connector Solutions"
  rect 60x60 hole 40: 1(-50,50)
  round 60 hole 40: 2(50,50) 3(-50,-50) 4(50,-50)
  silkscreen extent -110,-110 110,135, body extent -110,-110 110,110, height 310
Tenma_SPC15354 [mm] "Insulated Banana Jack, Black"
  round 12 hole 6.858: 1(0,0)
  body extent -6.3,-6.34 6.35,6.34, height 8.8
Tenma_SPC15363 [mm] "Insulated Banana Jack, Red"
  round 12 hole 6.858: 1(0,0)
  body extent -6.3,-6.34 6.35,6.34, height 8.8
TERM_BLK_ED555-2DS [mil]
  rect 100x100 hole 50: 1(0,0)
  round 100 hole 50: 2(138,0)
  silkscreen extent -93,-161 215,113, body extent -69,-150 207,106, height 323
TERM_BLK_ED555-4DS [mm]
  rect 2.54x2.54 hole 1.27: 1(0,0)
  round 2.54 hole 1.27: 2(3.5,0) 3(7,0) 4(10.5,0)
  silkscreen extent -2.36,-4.09 12.25,2.67, body extent -1.75,-3.8 12.25,2.7, height 8.2
TI_Stacked_Overlay_Small [mil]
  silkscreen extent -418,-98 418,98
TSSOP-8 [mm] "TSSOP, 8-Leads, Body 3.1x4.5mm (max), Pitch 0.65mm, IPC Medium Density"
  rrect50% 1.7x0.35 smd: 1(-2.85,0.975) 2(-2.85,0.325) 3(-2.85,-0.325) 4(-2.85,-0.975) 5(2.85,-0.975) 6(2.85,-0.325) 7(2.85,0.325) 8(2.85,0.975)
  silkscreen extent -2.97,-1.55 1.6,1.82, body extent -3.2,-1.55 3.2,1.55, height 1.07

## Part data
C1 C16 C19 C21 C22: "CAP, CERM, 10 µF, 6.3 V, +/- 10%, X5R, 0805"
C2 C13: "CAP, CERM, 1uF, 50V, +/-10%, X7R, 0805"
C3: "CAP, AL, 330 µF, 50 V, +/- 20%, 0.028 ohm, TH"
C4 C8 C9 C11 C12: "CAP, CERM, 2.2uF, 16V, +/-10%, X7R, 0805"
C5 C10: "CAP, CERM, 0.22 µF, 50 V, +/- 10%, X7R, 0603"
C6 C7 C24 C25 C27 C28: "CAP, CERM, 0.1 µF, 100 V, +/- 10%, X7R, 0805"
C17 C18 C20 C23: "CAP, CERM, 0.1 µF, 16 V, +/- 10%, X7R, 0603"
C26 C29 C30: library part Capacitor, "CAP, CERM, xxxF, xxV, [TempCo], xx%, [PackageReference]"
C31: "CAP, CERM, 2200 pF, 50 V, +/- 10%, X7R, 0603"
C32: "CAP, CERM, 4.7 µF, 25 V, +/- 10%, X7R, 1206"
C33: "CAP, CERM, 0.082 µF, 25 V, +/- 10%, X7R, 0603"
C34 C38: "CAP, CERM, 0.1 µF, 25 V, +/- 10%, X7R, 0603"
C35: "CAP, CERM, 10 µF, 50 V, +/- 10%, X5R, 1206_190"
C36 C37: "CAP, TA, 4.7 µF, 35 V, +/- 10%, 0.6 ohm, SMD"
C39 C40 C41 C42 C43 C44 C52: "CAP, CERM, 0.1uF, 16V, +/-10%, X7R, 0402"
C45: "CAP, CERM, 10uF, 10V, +/-20%, X5R, 0603"
C46 C51: "CAP, CERM, 1uF, 6.3V, +/-20%, X5R, 0402"
C47 C48: "CAP, CERM, 47pF, 25V, +/-5%, C0G/NP0, 0402"
C49: "CAP, CERM, 100pF, 50V, +/-5%, C0G/NP0, 0402"
C50: "CAP, CERM, 1000pF, 50V, +/-5%, C0G/NP0, 0402"
D1: library part SMLP12BC7TT86, "LED, Blue, SMD"
FID1 FID2 FID3: "Fiducial mark.  There is nothing to buy or mount."
FL1: "Filter, EMI, 10A 50V 1MHZ-1GHZ SMD"
H1 H2 H3 H4: "Machine Screw, Round, #4-40 x 1/4, Nylon, Philips panhead"
H5 H6 H7 H8: "Standoff, Hex, 0.5\"L #4-40 Nylon"
J1: "Terminal Block, 6A, 3.5mm Pitch, 2-Pos, TH"
J2: "Header, 100mil, 2x1, Gold, TH"
J3: "Terminal Block, 6A, 3.5mm Pitch, 4-Pos, TH"
J4: "Audio Jack, 3.5mm, Stereo, R/A, Pink, SMT"
J5: library part SPC15363, "BANANA JACK, SOLDER LUG, RED, TH"
J6: library part SPC15354, "BANANA JACK, SOLDER LUG, BLACK, TH"
J8: library part PEC02DAAN, "Header, 100mil, 2x2, Tin, TH"
J9: library part DX4R205JJAR1800, "Connector, Receptacle, Micro-USB Type AB, R/A, Bottom Mount SMT"
J10 J11 J12 J13: library part PBC02SAAN, "Header, 100mil, 2x1, Gold, TH"
K1: "Relay, SPST-NO (1 Form A), 0.7 A, , SMD"
L1 L2: "Inductor, Shielded, Metal Composite, 15 µH, 2.7 A, 0.179 ohm, AEC-Q200 Grade 1, SMD"
L3: "Inductor, Shielded E Core, Ferrite, 10 µH, 7.2 A, 0.01 ohm, SMD"
Logo1: library part TI_Logo, "Texas Instrument Corporate Signature"
Logo2: library part Pb-Free
MK1: "Microphone, Electret Condenser, Omnidirectional, -44 dB, TH"
Q1: library part "MMBT2222A, Fairchild Semiconductor", "Transistor, NPN, 40V, 0.15A, SOT-23"
R1 R2 R11: "RES, 100k ohm, 5%, 0.1W, 0603"
R3 R4: "RES, 10k ohm, 5%, 0.1W, 0603"
R6 R10 R16 R17 R21 R26: "RES, 0, 5%, 0.1 W, 0603"
R8: "RES, 100 k, 5%, 0.1 W, 0603"
R12 R13: "RES, 2.7 k, 5%, 0.1 W, 0603"
R14 R15: "RES, 2.2 k, 5%, 0.1 W, 0603"
R18 R29 R36 R39 R41: "RES, 0, 5%, 0.063 W, 0402"
R19: "RES, 4.99 k, 1%, 0.1 W, 0603"
R20 R38: "RES, 100k ohm, 1%, 0.063W, 0402"
R24 R25: "RES, 4.99k ohm, 1%, 0.063W, 0402"
R27: "RES, 15.0k ohm, 1%, 0.063W, 0402"
R28 R30 R33 R35: "RES, 49.9 ohm, 1%, 0.063W, 0402"
R31: "RES, 1.50k ohm, 1%, 0.063W, 0402"
R32 R34: "RES, 27.4 ohm, 1%, 0.063W, 0402"
R37: "RES, 3.09k ohm, 1%, 0.063W, 0402"
R40: "RES, 10.0 k, 1%, 0.063 W, 0402"
R42: "RES, 360 ohm, 5%, 0.063W, 0402"
TP1 TP2: "Test Point, Compact, Yellow, TH"
TP3 TP4 TP5 TP6 TP7 TP8 TP9 TP10 TP11 TP12: library part 5009, "Test Point, Compact, Yellow, TH"
TP13 TP14 TP15 TP16: library part 5006, "Test Point, Compact, Black, TH"
U1: "ESD Protection Array for AC Signal Data Interface, 2 Channels, -40 to +85 degC, 3-pin SC70 (DCK), Green (RoHS & no Sb/Br)"
U2: "8-W Mono Automotive Digital-Audio Amplifier With Load Dump and I2C Diagnostics, PWP0016B"
U3: "LOW-POWER STEREO AUDIO CODEC, RHB0032E"
U4: "High Voltage Ultra Low Iq - Low Drop Out Regulator, DCY0004A"
U5: "Single Output Automotive LDO, 100 mA, Fixed 1.8 V Output, 2.7 to 10 V Input, 5-pin SOT-23 (DBV), -40 to 125 degC, Green (RoHS & no Sb/Br)"
U6: "EEPROM, 512KBIT, 400KHZ, 8TSSOP"
U9: "IC, USB Streaming Controller"
Y1: "Oscillator, 6MHz, 3.3V, SMD"
ZZ1 ZZ2 ZZ3: library part AssemblyNote

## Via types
v1: diameter 24, hole 12, Top Layer to Bottom Layer, tented both sides, 188 vias
v2: diameter 15.75, hole 7.87, Top Layer to Bottom Layer, tented both sides, 18 vias
v3: diameter 19.68, hole 7.87, Top Layer to Bottom Layer, 5 vias
v4: diameter 20, hole 10, Top Layer to Bottom Layer, tented both sides, 2 vias

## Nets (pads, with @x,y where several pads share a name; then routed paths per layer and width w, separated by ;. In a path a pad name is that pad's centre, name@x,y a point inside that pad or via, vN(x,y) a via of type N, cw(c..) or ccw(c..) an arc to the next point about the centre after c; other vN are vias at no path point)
1.8V: C16.1 C17.1 C36.1 TP10.1 U3.32 U5.5 | length 1925.7
  Top Layer w40: TP10.1@1500,2755 1500,2677 1570.44,2606.56 C36.1@1730.55,2606.56
  Bottom Layer w40: v1(1700,2510) 1700,1700 1753,1647 2154,1647 2199.75,1601.25 2199.75,1364.25 v1(2200,1364)
3.3V: C18.1 C19.1 C20.1 C21.1 C22.1 C23.1 C37.1 C38.1 K1.4 R1.1 R2.1 R3.1 R4.1 R8.2 R12.1 R13.1 R24.2 R25.2 TP9.1 U3.7 U3.18 U3.24 U3.25 U4.3 U5.1 | length 4342
  Top Layer w10: v1(1836,1549) 1836,1497.5 R13.1@1851,1482.5 1865,1496.5 v1(1865,1549) ; 2011,1349 2015.79,1344.21 U3.7@2015.79,1289.49 ; C20.1@2015.71,1037.46 U3.18@2015.71,1101.49 ; C20.1@2020,1045.97 C20.1@2028.51,1037.46 ; v1(2075,1020) 2070,1025 2040.97,1025 C20.1@2028.51,1037.46 ; v1(2075,1050) 2041.05,1050 C20.1@2028.51,1037.46 ; v1(2090,939.56) 2054.92,939.56 C21.1@2037.01,957.46 ; v1(2090,976.09) 2055.64,976.09 C21.1@2037.01,957.46 ; v1(2138,1416) 2112.47,1416 2111.47,1417 2099.47,1405 C22.1@2087.01,1417.46 2118.55,1449 v1(2138,1449) ; v1(2430,1435) 2405.68,1435 R8.2@2394.2,1446.48 2407.72,1460 v1(2430,1460) ; C20.1@2028.51,1037.46 2028.51,965.96 C21.1@2037.01,957.46
  Top Layer w20: v1(960,1835) 961,1834 R24.2@993.31,1834 ; R25.2@1117.69,1833 1163,1833 1185,1855 1185,2045 1210,2070 1350,2070 1420,2000 K1.4@1530.24,2000 ; R12.1@1944,1481.5 1952.5,1481.5 2012.5,1421.5 C23.1@2017,1421.5 ; 2011,1349 2003,1357 2003,1401.95 2017.01,1415.96 2085.52,1415.96 C22.1@2087.01,1417.46
  Top Layer w25: v1(2895,1740) 2941.5,1740 R3.1@2943.5,1738 R4.1@2943.5,1681 ; R2.1@3246.5,1459 3247.5,1460 R1.1@3348.5,1460 3348.5,1411.5 v1(3350,1410)
  Signal Layer 2 w25: 2286,1010 2431,1010 2578,1157 3097,1157 v1(3350,1410) 3412.38,1472.38 3412.38,1722.62 3315,1820 3045,1820 2960,1735 2955,1740 v1(2895,1740)
  Bottom Layer w20: v1(960,1835) v1(1150,1835)
  other v1: 2210,980 2245,980 2180,1005 2180,1040 1650,2080 1650,2185 1650,2225 1650,2260 1650,2290
3.3V-USB: C39.1 C40.1 C41.1 C42.1 C43.1 C44.1 C45.1 C46.2 K1.3 R20.2 R38.2 R40.2 R42.1 TP11.1 U6.8 U9.2 U9.8 U9.21 U9.33 Y1.1 Y1.4 | length 4101
  Top Layer w10: v1@535,2104.37 551.3,2088.07 U6.8@607.2,2088.07 643.7,2088.07 659.69,2104.06 R20.2@675,2104.06 TP11.1@675,2750 ; R38.2@839,1093.69 845.79,1100.47 U9.8@908.35,1100.47 908.82,1100 v1(1000,1100) ; U9.2@908.35,1218.58 986.42,1218.58 v1(990,1215) ; v1(930,1490) 933.11,1486.89 Y1.1@933.11,1443.46 ; R42.1@964.69,780.32 964.69,745.31 v1(965,745) ; v1(985,1490) 986.26,1488.74 Y1.4@986.26,1443.46 ; R40.2@1009.69,780.32 1009.69,745.31 v1(1010,745) ; U9.21@1123.9,963.66 1123.9,1043.9 v1(1125,1045) ; v1(1160,1180) 1160.79,1179.21 U9.33@1241.02,1179.21
  Signal Layer 2 w30: v1(540,2094.37) 540,1954.37 709.37,1785 1010,1785 1015,1780 1015,1520 v1(985,1490) v1(930,1490) 930,1275 v1(990,1215) 1000,1205 1000,1104.75 1059.75,1045 v1(1125,1045) ; v1(965,745) v1(1010,745) 1013.58,745 1125,856.42 v1(1125,1045) ; 1015,1785 1204.25,1785 1259.25,1840 v1(1565,1840) ; v1(1160,1180) 1150.13,1170.13 1150.13,1070.13 v1(1125,1045)
  other v1: 1280,1840 1345,1840 1410,1840 1485,1840
5V-USB: J9.1 R19.2 R27.1 | length 1307.3
  Top Layer w10: J9.1@194.29,1466.18 194.29,1467.72 383.03,1467.72 R27.1@400.32,1485 400.32,1524.68 v1(400,1525)
  Top Layer w20: v1(1240,1905) R19.2@1240,1942.44
  Bottom Layer w20: v1(400,1525) 405,1530 895,1530 1240,1875 v1(1240,1905)
BCLK: J11.1 R36.1 U3.2 | length 2540.9
  Top Layer w10: R36.1@1467.68,1424 1504,1424 v1(1505,1425) ; U3.2@2114.21,1289.49 2114.21,1339.21 v1(2123,1348) v1@2128,1348
  Bottom Layer w10: v1(1505,1425) 1505,1455.28 1538.72,1489 2020.82,1489 2126,1383.82 2126,1345 2099.25,1318.25 1952.97,1318.25 1885,1250.28 1885,443 2049,279 2314,279 2350,243 J11.1@2350,190
DM: C48.2 R32.2 U9.7 | length 817.1
  Top Layer w10: R32.2@289.69,1445 v1@405.28,1445 ; v4@762.13,1112.87 v4(760,1115) 789.69,1115 C48.2@795,1109.69 ; C48.2@800,1112.87 800,1120 908.19,1120 U9.7@908.35,1120.16
  Bottom Layer w10: v1(400,1440) 395.13,1435.13 395.13,1385.13 395,1385 395,1365 402.13,1357.87 402.13,1357.6 622.6,1137.13 622.87,1137.13 635,1125 750,1125 v4(760,1115)
DP: C47.2 R31.2 R34.2 U9.6 | length 753.7
  Top Layer w10: R34.2@289.69,1410 R31.2@400.31,1410 400.31,1404.69 420,1385 v1(420,1380) ; v4(760,1155) 768,1147 793,1147 800.16,1139.84 U9.6@908.35,1139.84
  Bottom Layer w10: v1(420,1380) 420,1365 630,1155 630.28,1155 640.28,1145 750,1145 v4(760,1155)
GND: C1.2 C2.2 C3.2 C4.1 C11.2 C13.2 C16.2 C17.2 C18.2 C19.2 C20.2 C21.2 C22.2 C23.2 C26.2 C29.2 C30.2 C31.2 C32.2 C33.2 C34.2 C35.2 C36.2 C37.2 C38.2 C39.2 C40.2 C41.2 C42.2 C43.2 C44.2 C45.2 C46.1 C47.1 C48.1 C51.1 C52.2 FL1.4 FL1.5 FL1.6 J2.1 J4.1 J8.2 J8.4 J9.5 J9.6 J9.7 J9.8 J9.9 J10.2 J11.2 J12.2 J13.2 K1.2 MK1.1 R11.1 R18.1 R21.2 R26.2 TP13.1 TP14.1 TP15.1 TP16.1 U1.3 U2.1 U2.9 U2.16 U2.17 U3.6 U3.17 U3.21 U3.26 U3.33 U4.2 U4.4 U5.2 U6.1 U6.2 U6.3 U6.4 U9.4 U9.10 U9.11 U9.16 U9.28 U9.45 Y1.2 | length 1707.7
  Top Layer w10: v1(160,1010) 160,955 163.54,951.46 J4.1@204.02,951.46 ; J9.5@194.29,1363.82 248.82,1363.82 v1(250,1365) ; v1(200,1010) 200,955.47 J4.1@204.02,951.46 ; v1(240,1010) 240,951.46 J4.1@204.02,951.46 ; v1(620,1250) R26.2@660.44,1250 ; R21.2@720,2121.93 v1(720,2164.37) ; v1(760,1190) 760.32,1189.68 C47.1@795,1189.68 ; v1(795,1034) C48.1@795,1070.32 ; v1(834,936) C51.1@834,976.32 ; v1(890,1375) 931.57,1375 Y1.2@933.11,1376.54 ; U9.11@908.35,1041.42 958.58,1041.42 v1(965,1035) ; U9.10@908.35,1061.1 956.1,1061.1 v1(965,1070) ; U9.4@908.35,1179.21 959.21,1179.21 v1(960,1180) ; v1(1025,1240) 1025.47,1240.47 U9.45@1025.47,1296.34 ; U9.16@1025.47,963.66 1026.38,962.76 1026.38,923.62 1049.37,900.63 C52.2@1049.37,895 1050,894.37 v1(1050,855) ; v1(1185,1080) 1185.79,1080.79 U9.28@1241.02,1080.79 ; v1(1355,2340) C37.2@1396.5,2340 ; v1(1355,2375) C37.2@1431.5,2375 ; v1(1355,2410) C37.2@1396.5,2410 ; v1(1730,1035) 1771.06,1035 C30.2@1778.5,1042.44 ; C36.2@1954.12,2570 v1(1990,2570) ; v1(1990,2605) 1919.12,2605 C36.2@1917.56,2606.56 1951,2640 v1(1990,2640) ; U3.33@2035.68,1221.97 U3.6@2035.68,1289.88 ; U3.21@2074.9,1103.44 U3.33@2074.9,1161.24 ; U3.33@2116.43,1146.23 U3.26@2164.65,1146.23 ; U1.3@2369.29,1295 v1(2415,1295) ; v1(2875,1790) 2912,1790 C13.2@2931,1809 2910,1830 v1(2875,1830)
  other v1: 1765,850 1800,850 1965,895 2005,895 2375,1075 1965,1090 2375,1105 2362,1140 2440,1140 2224,1141 2296,1141 2480,1175 2288,1211 2360,1211 2420,1225 2525,1225 1615,1258 2460,1265 2550,1268 2475,1325 2550,1326 2475,1385 2550,1385 2475,1445 2550,1445 2590,1470 2645,1470 2475,1510 3365,1530 2510,1545 2120,1550 2060,1551 2015,1552 2243,1555 2280,1555 2550,1570 2595,1570 2645,1570 4030,1610 4080,1610 4130,1610 4180,1610 1770,1690 1805,1690 1840,1690 3240,1710 3365,1710 1225,1725 1280,1735 1325,1735 1370,1735 1415,1735 1460,1735 1505,1735 1550,1735 3235,1780 1770,1805 1805,1805 1840,1805 1770,1840 1805,1840 1840,1840 1365,1900 1780,1905 1815,1905 1780,1935 1815,1935 445,2009.69 445,2049.69 1780,2050 1815,2050 445,2089.69 1775,2090 1820,2090 1805,2200 1805,2235 1780,2275 2755,2410 1805,2420 2755,2455 2755,2505 2650,2535 3195,2555 2300,2585 2500,2585 2650,2600 3195,2600 2375,2640 2425,2640 3195,2650 2650,2675 2650,2750 2650,2825
  other v2: 3270,1570 3300,1570 3330,1570 3270.47,1590.47 3300,1590 3329.53,1590.47 3270,1610 3300,1610 3330,1610 3270,1630 3300,1630 3330,1630 3270.47,1649.53 3300,1650 3329.53,1649.53 3270,1670 3300,1670 3330,1670
  other v3: 2065,1136.93 2006.93,1195 2065,1195 2123.07,1195 2065,1253.07
MCLK: J10.1 R29.1 U3.1 | length 2915.4
  Top Layer w10: R29.1@1467.68,1519 1516.75,1519 v1(1520,1515.75) ; U3.1@2133.9,1289.49 2133.9,1313.9 2160,1340 2160,1352 v1(2155,1357)
  Bottom Layer w10: v1(1520,1515.75) 1520,1519 1522,1517 2110.18,1517 2162.87,1464.3 2162.87,1364.87 v1(2155,1357) ; v1@2156,1357 2156,1332.89 2123.48,1300.37 1960.37,1300.37 1905,1245 1905,451 2055,301 2613,301 2650,264 J10.1@2650,190
NetC4_2: C4.2 J1.2 L1.2
NetC5_1: C5.1 L1.1 U2.12
NetC5_2: C5.2 U2.13 | length 158.3
  Top Layer w10: U2.13@3416.14,1632.8 3472.8,1632.8 3475.13,1635.13 3475.3,1635.13 3489.87,1649.7 3489.87,1649.87 3531.5,1691.5 C5.2@3550,1691.5
NetC6_1: C6.1 J3.2 | length 166.4
  Top Layer w15: J3.2@887.8,155 890,157.2 C6.1@890,320.5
